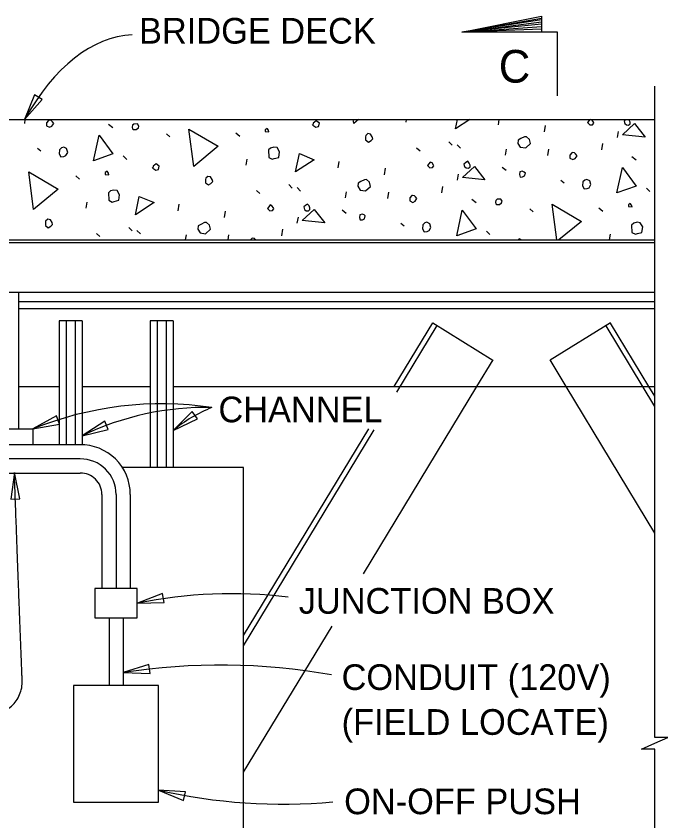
# Model space of a CAD drawing. Extents: x 927736.2 to 927809.6, y 636703.6 to 636757.7.
# Drawn here: x 927764.73 to 927774.19, y 636721.33 to 636733.02 of the extents above; entities that cross this region are included whole.
import ezdxf

# ---------------------------------------------------------------- set-up
doc = ezdxf.new("R2010")
doc.units = 0
for name, color, linetype in [('DimLines_dp', 7, 'Continuous'), ('Miscellaneous1', 7, 'Continuous'), ('Miscellaneous2', 7, 'Continuous'), ('Miscellaneous3', 7, 'Continuous')]:
    doc.layers.add(name, color=color, linetype=linetype)

msp = doc.modelspace()

# ---------------------------------------------------------------- linework, layer by layer
at = {"layer": 'DimLines_dp'}
for p, q in [((927771.201, 636732.786), (927772.357, 636732.99)), ((927772.357, 636732.965), (927771.201, 636732.786)), ((927771.201, 636732.786), (927772.357, 636732.934)), ((927772.357, 636732.901), (927771.201, 636732.786)), ((927771.201, 636732.786), (927772.357, 636732.867)), ((927772.357, 636732.83), (927771.201, 636732.786))]:
    msp.add_line(p, q, dxfattribs=at)
for points in [[(927772.589, 636731.861), (927772.589, 636732.786), (927771.201, 636732.786), (927772.357, 636733.018), (927772.357, 636732.786)], [(927774, 636713.104), (927774, 636722.378), (927773.809, 636722.378), (927774, 636722.461), (927774.191, 636722.544), (927774, 636722.544), (927774, 636731.999)]]:
    msp.add_lwpolyline(points, dxfattribs=at)
for points in [[(927764.852, 636731.515), (927765.11, 636731.808), (927764.999, 636731.877)], [(927767.01, 636727), (927767.362, 636727.17), (927767.286, 636727.277)], [(927764.974, 636727.024), (927765.359, 636727.094), (927765.315, 636727.216)], [(927765.688, 636726.926), (927766.068, 636727.016), (927766.018, 636727.136)], [(927764.705, 636726.393), (927764.654, 636726.006), (927764.785, 636726.011)], [(927766.491, 636724.495), (927766.881, 636724.507), (927766.855, 636724.635)], [(927766.285, 636723.488), (927766.675, 636723.474), (927766.658, 636723.603)], [(927766.799, 636721.782), (927767.159, 636721.632), (927767.189, 636721.759)]]:
    msp.add_lwpolyline(points, close=True, dxfattribs=at)
for centre, radius, start, end in [((927766.848, 636722.389), 5, 81.6635, 112.0069), ((927767.492, 636723.175), 4.162, 88.8828, 115.6789), ((927768.324, 636725.436), 2.043, 111.5678, 130.0212), ((927767.852, 636717.791), 6.841, 83.0445, 101.4782), ((927767.692, 636714.325), 9.271, 79.9649, 98.7311), ((927768.59, 636729.517), 7.939, 256.9627, 275.3449)]:
    msp.add_arc(centre, radius, start, end, dxfattribs=at)
msp.add_ellipse((927766.69, 636726.905), major_axis=(0.274, -5.84), ratio=0.464296, start_param=3.141604, end_param=3.781059, dxfattribs=at)
msp.add_open_spline([(927758.883, 636722.628), (927762.516, 636722.653), (927764.844, 636722.779), (927764.793, 636724), (927764.705, 636726.393)], degree=2, dxfattribs=at)
at = {"layer": 'Miscellaneous1'}
for p, q in [((927765.354, 636728.592), (927765.354, 636726.795)), ((927765.688, 636728.592), (927765.354, 636728.592)), ((927765.457, 636728.592), (927765.457, 636726.795)), ((927765.586, 636728.592), (927765.586, 636726.795)), ((927765.688, 636728.592), (927765.688, 636726.795)), ((927767.01, 636728.592), (927766.676, 636728.592)), ((927766.676, 636728.592), (927766.676, 636726.463)), ((927766.778, 636728.592), (927766.778, 636726.463)), ((927766.907, 636728.592), (927766.907, 636726.463)), ((927767.01, 636728.592), (927767.01, 636726.463)), ((927764.139, 636727.024), (927764.974, 636727.024)), ((927764.974, 636727.024), (927764.974, 636726.795)), ((927765.656, 636726.795), (927764.242, 636726.795)), ((927765.66, 636726.589), (927764.242, 636726.59)), ((927764.242, 636726.384), (927765.662, 636726.383)), ((927765.976, 636726.075), (927765.976, 636724.707)), ((927766.182, 636726.075), (927766.182, 636724.707)), ((927766.388, 636726.075), (927766.388, 636724.707)), ((927766.079, 636724.283), (927766.079, 636723.302)), ((927766.285, 636724.283), (927766.285, 636723.302))]:
    msp.add_line(p, q, dxfattribs=at)
for points in [[(927766.49, 636724.707), (927765.874, 636724.707), (927765.874, 636724.283), (927766.49, 636724.283)], [(927766.799, 636723.302), (927765.565, 636723.302), (927765.565, 636721.607), (927766.799, 636721.607)]]:
    msp.add_lwpolyline(points, close=True, dxfattribs=at)
for radius, end in [(0.72, 90.9434), (0.514, 90.8699), (0.308, 91.129)]:
    msp.add_arc((927765.668, 636726.075), radius, 0, end, dxfattribs=at)
at = {"layer": 'Miscellaneous2'}
for p, q in [((927753.063, 636731.515), (927774, 636731.515)), ((927764.855, 636731.46), (927764.863, 636731.515)), ((927770.393, 636731.476), (927770.399, 636731.515)), ((927771.731, 636731.438), (927771.742, 636731.515)), ((927766.072, 636731.448), (927766.135, 636731.401)), ((927772.402, 636731.337), (927772.416, 636731.43)), ((927773.458, 636731.256), (927773.473, 636731.343)), ((927766.913, 636731.309), (927766.963, 636731.265)), ((927767.918, 636731.323), (927767.976, 636731.275)), ((927765.041, 636731.101), (927765.089, 636731.063)), ((927770.542, 636731.107), (927770.593, 636731.063)), ((927771.011, 636731.194), (927771.062, 636731.144)), ((927771.131, 636731.15), (927771.183, 636731.1)), ((927773.232, 636731.075), (927773.246, 636731.168)), ((927766.284, 636730.988), (927766.336, 636730.938)), ((927771.835, 636731), (927771.85, 636731.087)), ((927772.45, 636730.993), (927772.463, 636731.086)), ((927768.07, 636730.853), (927768.085, 636730.94)), ((927769.407, 636730.816), (927769.421, 636730.909)), ((927773.666, 636730.98), (927773.73, 636730.933)), ((927770.079, 636730.715), (927770.093, 636730.808)), ((927771.786, 636730.827), (927771.843, 636730.779)), ((927765.595, 636730.701), (927765.653, 636730.652)), ((927771.135, 636730.634), (927771.15, 636730.721)), ((927772.636, 636730.634), (927772.684, 636730.596)), ((927768.688, 636730.572), (927768.739, 636730.522)), ((927768.808, 636730.528), (927768.86, 636730.478)), ((927770.909, 636730.452), (927770.923, 636730.545)), ((927773.879, 636730.52), (927773.931, 636730.47)), ((927768.219, 636730.485), (927768.269, 636730.441)), ((927769.512, 636730.378), (927769.527, 636730.465)), ((927770.127, 636730.37), (927770.14, 636730.463)), ((927765.747, 636730.231), (927765.762, 636730.318)), ((927767.084, 636730.193), (927767.098, 636730.286)), ((927771.343, 636730.358), (927771.407, 636730.311)), ((927767.756, 636730.092), (927767.77, 636730.185)), ((927769.463, 636730.205), (927769.52, 636730.157)), ((927772.185, 636730.219), (927772.235, 636730.175)), ((927773.19, 636730.233), (927773.247, 636730.185)), ((927768.812, 636730.012), (927768.827, 636730.099)), ((927766.365, 636729.949), (927766.416, 636729.899)), ((927770.313, 636730.011), (927770.361, 636729.973)), ((927765.896, 636729.862), (927765.946, 636729.818)), ((927766.485, 636729.905), (927766.537, 636729.855)), ((927767.191, 636729.768), (927767.204, 636729.842)), ((927767.807, 636729.768), (927767.817, 636729.841)), ((927768.586, 636729.83), (927768.6, 636729.923)), ((927771.556, 636729.898), (927771.608, 636729.848)), ((927773.342, 636729.768), (927773.356, 636729.85)), ((927762.11, 636729.768), (927774, 636729.768)), ((927762.121, 636729.73), (927774, 636729.73)), ((927760.453, 636729.01), (927774, 636729.01))]:
    msp.add_line(p, q, dxfattribs=at)
for points in [[(927765.172, 636731.469), (927765.171, 636731.424), (927765.215, 636731.403), (927765.249, 636731.419), (927765.277, 636731.458), (927765.257, 636731.485), (927765.241, 636731.5), (927765.213, 636731.505), (927765.202, 636731.502), (927765.172, 636731.469)], [(927766.421, 636731.382), (927766.436, 636731.373), (927766.475, 636731.371), (927766.506, 636731.398), (927766.513, 636731.419), (927766.492, 636731.452), (927766.441, 636731.451), (927766.42, 636731.433), (927766.415, 636731.406), (927766.421, 636731.382)], [(927769.038, 636731.432), (927769.083, 636731.406), (927769.119, 636731.415), (927769.132, 636731.463), (927769.085, 636731.495), (927769.064, 636731.477), (927769.042, 636731.465), (927769.038, 636731.432), (927769.035, 636731.444)], [(927769.632, 636731.457), (927769.624, 636731.515)], [(927769.702, 636731.515), (927769.632, 636731.457)], [(927771.108, 636731.38), (927771.137, 636731.515)], [(927771.318, 636731.515), (927771.108, 636731.38)], [(927773.024, 636731.472), (927773.059, 636731.437), (927773.096, 636731.44), (927773.115, 636731.465), (927773.112, 636731.476), (927773.091, 636731.509), (927773.075, 636731.515)], [(927773.058, 636731.515), (927773.043, 636731.496), (927773.024, 636731.472)], [(927773.531, 636731.295), (927773.705, 636731.457), (927773.859, 636731.262), (927773.531, 636731.295)], [(927773.581, 636731.515), (927773.575, 636731.511), (927773.555, 636731.493), (927773.564, 636731.457)], [(927773.564, 636731.457), (927773.588, 636731.438), (927773.621, 636731.434), (927773.642, 636731.452), (927773.642, 636731.478), (927773.628, 636731.506), (927773.621, 636731.515)], [(927767.308, 636730.834), (927767.24, 636731.378), (927767.664, 636731.128), (927767.308, 636730.834)], [(927768.347, 636731.342), (927768.399, 636731.337), (927768.393, 636731.361), (927768.373, 636731.388), (927768.347, 636731.368), (927768.347, 636731.342)], [(927765.856, 636730.918), (927765.935, 636731.29), (927766.136, 636731.018), (927765.856, 636730.918)], [(927769.804, 636731.267), (927769.803, 636731.222), (927769.844, 636731.188), (927769.882, 636731.211), (927769.907, 636731.237), (927769.9, 636731.267), (927769.876, 636731.305), (927769.836, 636731.314), (927769.805, 636731.286), (927769.804, 636731.267)], [(927772.013, 636731.169), (927772.047, 636731.115), (927772.127, 636731.104), (927772.199, 636731.168), (927772.183, 636731.228), (927772.14, 636731.267), (927772.109, 636731.265), (927772.058, 636731.239), (927772.02, 636731.216), (927772.013, 636731.169)], [(927765.36, 636731.078), (927765.356, 636731.02), (927765.381, 636730.975), (927765.424, 636730.981), (927765.452, 636730.995), (927765.479, 636731.04), (927765.464, 636731.094), (927765.421, 636731.114), (927765.391, 636731.106), (927765.36, 636731.078)], [(927768.393, 636731.074), (927768.397, 636730.966), (927768.448, 636730.942), (927768.478, 636730.95), (927768.543, 636730.967), (927768.554, 636731.047), (927768.519, 636731.108), (927768.472, 636731.114), (927768.424, 636731.101), (927768.393, 636731.074)], [(927768.785, 636730.757), (927768.842, 636731.022), (927769.057, 636730.933), (927768.785, 636730.757)], [(927772.767, 636731.001), (927772.766, 636730.956), (927772.81, 636730.936), (927772.844, 636730.951), (927772.872, 636730.991), (927772.852, 636731.017), (927772.835, 636731.032), (927772.808, 636731.038), (927772.796, 636731.034), (927772.767, 636731.001)], [(927766.715, 636730.809), (927766.76, 636730.783), (927766.796, 636730.793), (927766.809, 636730.841), (927766.762, 636730.873), (927766.741, 636730.855), (927766.719, 636730.842), (927766.715, 636730.809), (927766.712, 636730.821)], [(927770.701, 636730.85), (927770.736, 636730.814), (927770.773, 636730.818), (927770.792, 636730.842), (927770.789, 636730.854), (927770.768, 636730.887), (927770.739, 636730.898), (927770.72, 636730.874), (927770.701, 636730.85)], [(927771.241, 636730.835), (927771.265, 636730.816), (927771.298, 636730.812), (927771.319, 636730.83), (927771.319, 636730.855), (927771.305, 636730.884), (927771.285, 636730.91), (927771.252, 636730.889), (927771.231, 636730.87), (927771.241, 636730.835)], [(927764.985, 636730.212), (927764.916, 636730.755), (927765.341, 636730.505), (927764.985, 636730.212)], [(927766.024, 636730.72), (927766.076, 636730.715), (927766.07, 636730.739), (927766.05, 636730.765), (927766.024, 636730.745), (927766.024, 636730.72)], [(927771.208, 636730.673), (927771.382, 636730.834), (927771.536, 636730.639), (927771.208, 636730.673)], [(927772.039, 636730.716), (927772.048, 636730.681), (927772.08, 636730.683), (927772.108, 636730.697), (927772.122, 636730.739), (927772.106, 636730.754), (927772.077, 636730.765), (927772.041, 636730.755), (927772.039, 636730.716)], [(927773.451, 636730.45), (927773.53, 636730.822), (927773.73, 636730.55), (927773.451, 636730.45)], [(927767.481, 636730.644), (927767.48, 636730.599), (927767.521, 636730.566), (927767.559, 636730.589), (927767.584, 636730.615), (927767.576, 636730.644), (927767.553, 636730.683), (927767.513, 636730.691), (927767.482, 636730.664), (927767.481, 636730.644)], [(927769.69, 636730.547), (927769.724, 636730.492), (927769.804, 636730.481), (927769.876, 636730.545), (927769.86, 636730.605), (927769.817, 636730.645), (927769.786, 636730.643), (927769.735, 636730.616), (927769.697, 636730.593), (927769.69, 636730.547)], [(927772.955, 636730.611), (927772.951, 636730.552), (927772.976, 636730.508), (927773.019, 636730.513), (927773.047, 636730.527), (927773.073, 636730.572), (927773.059, 636730.626), (927773.015, 636730.646), (927772.986, 636730.638), (927772.955, 636730.611)], [(927766.07, 636730.452), (927766.074, 636730.344), (927766.125, 636730.319), (927766.155, 636730.327), (927766.22, 636730.345), (927766.231, 636730.424), (927766.195, 636730.485), (927766.149, 636730.492), (927766.101, 636730.479), (927766.07, 636730.452)], [(927766.462, 636730.135), (927766.519, 636730.399), (927766.734, 636730.31), (927766.462, 636730.135)], [(927770.444, 636730.379), (927770.443, 636730.334), (927770.487, 636730.313), (927770.521, 636730.329), (927770.549, 636730.368), (927770.529, 636730.395), (927770.512, 636730.41), (927770.485, 636730.415), (927770.473, 636730.412), (927770.444, 636730.379)], [(927768.918, 636730.212), (927768.942, 636730.193), (927768.975, 636730.189), (927768.996, 636730.208), (927768.995, 636730.233), (927768.982, 636730.261), (927768.962, 636730.288), (927768.929, 636730.266), (927768.908, 636730.248), (927768.918, 636730.212)], [(927771.693, 636730.292), (927771.708, 636730.283), (927771.747, 636730.281), (927771.778, 636730.308), (927771.785, 636730.329), (927771.764, 636730.362), (927771.713, 636730.361), (927771.692, 636730.343), (927771.687, 636730.316), (927771.693, 636730.292)], [(927772.577, 636729.768), (927772.511, 636730.288), (927772.936, 636730.038), (927772.609, 636729.768)], [(927773.619, 636730.252), (927773.671, 636730.247), (927773.665, 636730.271), (927773.645, 636730.298), (927773.618, 636730.278), (927773.619, 636730.252)], [(927768.378, 636730.227), (927768.413, 636730.192), (927768.45, 636730.195), (927768.469, 636730.22), (927768.466, 636730.232), (927768.444, 636730.264), (927768.416, 636730.276), (927768.397, 636730.251), (927768.378, 636730.227)], [(927768.885, 636730.05), (927769.059, 636730.212), (927769.213, 636730.017), (927768.885, 636730.05)], [(927771.128, 636729.828), (927771.207, 636730.2), (927771.407, 636729.928), (927771.128, 636729.828)], [(927765.158, 636730.022), (927765.157, 636729.977), (927765.198, 636729.943), (927765.236, 636729.966), (927765.261, 636729.992), (927765.253, 636730.022), (927765.23, 636730.06), (927765.19, 636730.069), (927765.159, 636730.041), (927765.158, 636730.022)], [(927769.716, 636730.094), (927769.725, 636730.058), (927769.757, 636730.06), (927769.785, 636730.074), (927769.799, 636730.116), (927769.782, 636730.131), (927769.754, 636730.143), (927769.718, 636730.133), (927769.716, 636730.094)], [(927767.367, 636729.924), (927767.401, 636729.87), (927767.48, 636729.859), (927767.553, 636729.923), (927767.537, 636729.983), (927767.494, 636730.022), (927767.463, 636730.02), (927767.412, 636729.994), (927767.374, 636729.971), (927767.367, 636729.924)], [(927770.632, 636729.988), (927770.628, 636729.93), (927770.653, 636729.885), (927770.696, 636729.891), (927770.724, 636729.905), (927770.75, 636729.95), (927770.736, 636730.003), (927770.692, 636730.024), (927770.662, 636730.016), (927770.632, 636729.988)], [(927773.665, 636729.984), (927773.669, 636729.876), (927773.72, 636729.852), (927773.75, 636729.86), (927773.815, 636729.877), (927773.826, 636729.957), (927773.79, 636730.017), (927773.744, 636730.024), (927773.696, 636730.011), (927773.665, 636729.984)], [(927768.209, 636729.768), (927768.206, 636729.772), (927768.189, 636729.787), (927768.162, 636729.793), (927768.15, 636729.789), (927768.132, 636729.768)], [(927772.055, 636729.768), (927772.034, 636729.783), (927772.017, 636729.768)]]:
    msp.add_lwpolyline(points, dxfattribs=at)
at = {"layer": 'Miscellaneous3'}
for p, q in [((927764.769, 636727.024), (927764.769, 636729.01)), ((927764.769, 636728.875), (927774, 636728.875)), ((927764.769, 636728.772), (927774, 636728.772)), ((927770.219, 636727.641), (927770.777, 636728.564)), ((927770.777, 636728.564), (927771.65, 636728.021)), ((927773.356, 636728.564), (927772.483, 636728.021)), ((927773.915, 636727.641), (927773.36, 636728.559)), ((927770.259, 636727.559), (927770.843, 636728.524)), ((927774, 636727.351), (927773.294, 636728.519)), ((927771.42, 636727.641), (927771.654, 636728.027)), ((927772.713, 636727.641), (927772.48, 636728.027)), ((927764.769, 636727.641), (927765.354, 636727.641)), ((927765.688, 636727.641), (927766.676, 636727.641)), ((927767.01, 636727.641), (927774, 636727.641)), ((927769.775, 636724.921), (927771.42, 636727.641)), ((927774, 636725.514), (927772.713, 636727.641)), ((927774, 636727.5), (927773.915, 636727.641)), ((927768.032, 636724.026), (927769.848, 636727.028)), ((927768.032, 636723.877), (927769.929, 636727.014)), ((927768.032, 636722.04), (927769.316, 636724.163))]:
    msp.add_line(p, q, dxfattribs=at)
msp.add_lwpolyline([(927768.032, 636718.446), (927768.032, 636718.446), (927768.032, 636726.463), (927766.275, 636726.463)], dxfattribs=at)

# ---------------------------------------------------------------- texts
at = {"layer": 'DimLines_dp'}
for s, height, p in [('BRIDGE DECK', 0.37296, (927766.515, 636732.618)), ('C', 0.474, (927771.736, 636732.052)), ('CHANNEL', 0.373, (927767.667, 636727.121)), ('JUNCTION BOX', 0.37296, (927768.833, 636724.342)), ('CONDUIT (120V)', 0.37296, (927769.455, 636723.235)), ('(FIELD LOCATE)', 0.37296, (927769.455, 636722.584)), ('ON-OFF PUSH ', 0.37296, (927769.492, 636721.432))]:
    msp.add_text(s, height=height, dxfattribs=at).set_placement(p)

doc.saveas('drawing.dxf')
